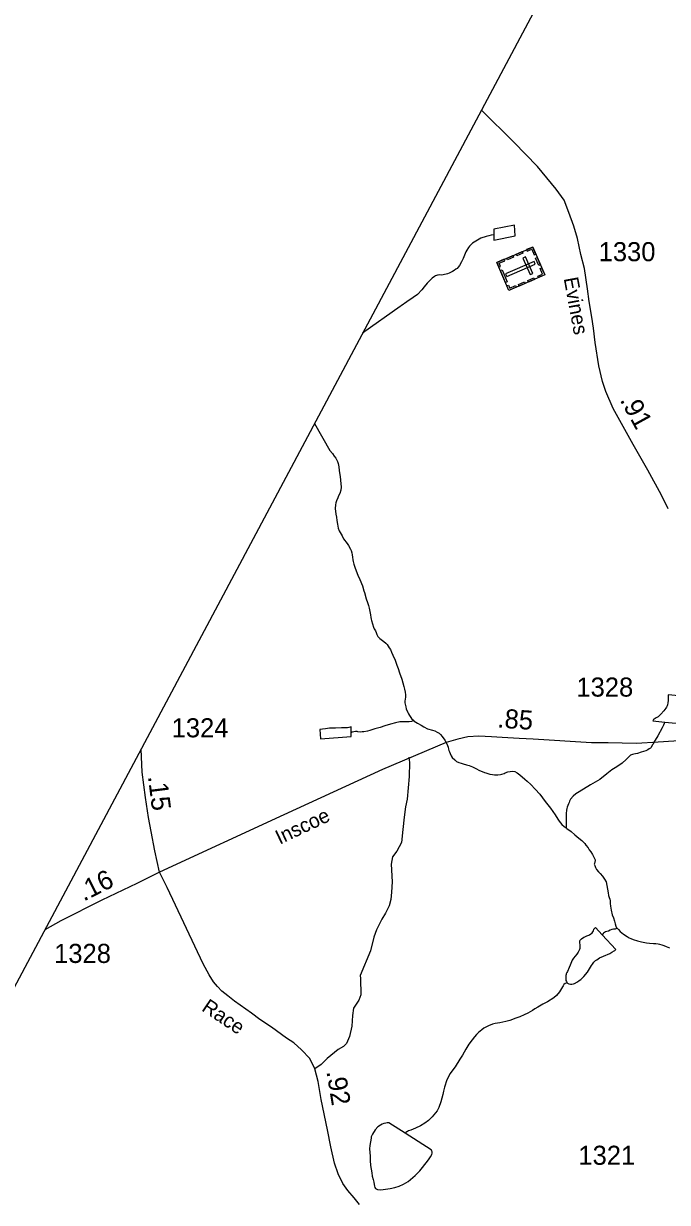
# Model space of a CAD drawing. Extents: x 2220236 to 2384410, y 720751 to 894131.
# Drawn here: x 2267666 to 2271879, y 844747 to 852462 of the extents above; entities that cross this region are included whole.
import ezdxf

# ---------------------------------------------------------------- set-up
doc = ezdxf.new("R2010")
doc.units = 0
for name, color, linetype in [('Exist Boundary Political CountyLine', 7, 'Continuous'), ('Exist Cultural Cemetery CELL', 7, 'Continuous'), ('Exist Hydrographic Creek Single Shore', 7, 'Continuous'), ('Exist Hydrographic Misc Water Feature', 7, 'Continuous'), ('Exist Hydrographic Pond Under 1500 Sq Ft', 7, 'Continuous'), ('Exist Road Non-System Type 51', 7, 'Continuous'), ('Exist Road Secondary Mileage Hundredths English Label', 7, 'Continuous'), ('Exist Road Secondary Type 51 Attributed', 7, 'Continuous'), ('Exist Road Secondary Type 51 Label', 7, 'Continuous'), ('Exist Road Secondary Type 51 Number Label', 7, 'Continuous')]:
    doc.layers.add(name, color=color, linetype=linetype)

msp = doc.modelspace()

# ---------------------------------------------------------------- linework, layer by layer
at = {"layer": 'Exist Boundary Political CountyLine'}
msp.add_lwpolyline([(2293117.8, 894131.3), (2291903.9, 891776.4), (2258821.6, 829664.6), (2255410.5, 823324), (2242088.6, 797598.7), (2231459.6, 775980.5), (2225010.8, 762953.2), (2220575.6, 753519.5)], dxfattribs=at)
at = {"layer": 'Exist Cultural Cemetery CELL'}
for points in [[(2270997.6, 850999.3), (2271076.4, 850816.5), (2270842.7, 850715.6), (2270763.8, 850898.4)], [(2270889.7, 850952.7), (2270929.5, 850969.9), (2270934, 850959.4), (2270894.2, 850942.3)], [(2270957.8, 850982.1), (2270962.3, 850971.7), (2270991.8, 850984.4), (2271007.9, 850947.2), (2271018.1, 850951.6), (2270997.6, 850999.3)], [(2270776.9, 850868), (2270787.5, 850872.6), (2270778.8, 850892.8), (2270815.9, 850908.8), (2270811.4, 850919), (2270763.8, 850898.4)], [(2271013.9, 850887.6), (2271006.5, 850904.7), (2270820.3, 850824.3), (2270827.7, 850807.2)], [(2270828, 850926.1), (2270867.7, 850943.3), (2270872.3, 850932.8), (2270832.5, 850915.7)], [(2270951.2, 850934.8), (2270934.1, 850927.4), (2270980.8, 850819.3), (2270997.9, 850826.7)], [(2271026.9, 850931.3), (2271047.4, 850883.7), (2271037, 850879.2), (2271016.4, 850926.7)], [(2270797.1, 850850.2), (2270830.7, 850772.2), (2270820.2, 850767.7), (2270786.6, 850845.6)], [(2271036.7, 850799.2), (2271032.2, 850809.6), (2271061.7, 850822.4), (2271045.6, 850859.6), (2271055.9, 850864), (2271076.4, 850816.4)], [(2270829.5, 850746), (2270840.1, 850750.5), (2270848.8, 850730.3), (2270885.9, 850746.4), (2270890.3, 850736.1), (2270842.7, 850715.6)], [(2270904.5, 850754.7), (2270944.3, 850771.8), (2270948.8, 850761.4), (2270909, 850744.2)], [(2270965, 850780.7), (2271004.8, 850797.9), (2271009.3, 850787.5), (2270969.6, 850770.3)]]:
    msp.add_lwpolyline(points, close=True, dxfattribs=at)
at = {"layer": 'Exist Hydrographic Creek Single Shore'}
for points in [[(2269569.9, 849844.6), (2269671.2, 849667.6), (2269687.5, 849647.6), (2269699.6, 849631.6), (2269708.9, 849617.6), (2269719.9, 849596.1), (2269723.9, 849581.9), (2269728.3, 849560.5), (2269730.4, 849535.8), (2269734.8, 849507.9), (2269736.9, 849498), (2269740.9, 849472.7), (2269743.6, 849428.3), (2269741.6, 849408.7), (2269735.9, 849386.5), (2269728, 849370.3), (2269722.2, 849358.2), (2269714.5, 849337.7), (2269709.7, 849324.7), (2269707.4, 849312.6), (2269706.7, 849306.1), (2269705.8, 849295.3), (2269705.6, 849285.4), (2269706.9, 849271.6), (2269708.8, 849251.9), (2269713.3, 849230.5), (2269715.5, 849209.8), (2269719.6, 849186.1), (2269725.9, 849160.4), (2269732.1, 849142.2), (2269738.1, 849129.9), (2269750.4, 849108.4), (2269760.5, 849088.5), (2269782.9, 849058.5), (2269793.1, 849045.2), (2269805.1, 849022.6), (2269809.1, 849012.7), (2269813.4, 848998.8), (2269817.4, 848984.6), (2269819.7, 848969.2), (2269821.7, 848952.7), (2269824, 848941.2), (2269828, 848924.7), (2269834.1, 848904.9), (2269842.5, 848880.8), (2269854.6, 848851), (2269866.9, 848823.9), (2269883.4, 848781.5), (2269893.5, 848749.5), (2269897.6, 848738), (2269907.8, 848695.8), (2269916.2, 848672), (2269922.4, 848653.8), (2269928.2, 848635.6), (2269932.7, 848614.2), (2269936.8, 848591.8), (2269939.1, 848573.7), (2269941.2, 848563.2), (2269942.7, 848555.6), (2269955.8, 848510.4), (2269961.5, 848500.5), (2269969.1, 848487.8), (2269973.8, 848476.3), (2269978.1, 848464), (2269984.4, 848450.8), (2269992.1, 848442.4), (2269998.6, 848436.4), (2270014.4, 848424.6), (2270024.4, 848417.2), (2270036.3, 848406.1), (2270045, 848397), (2270051.7, 848387.7), (2270059.6, 848376.1), (2270066.9, 848365.4), (2270073.2, 848348.9), (2270083.2, 848327.4), (2270097.6, 848294.9), (2270109.8, 848263.5), (2270118.2, 848241.4), (2270126.1, 848213.3), (2270140.7, 848172), (2270147.1, 848147.9), (2270153.5, 848124.2), (2270159.3, 848106), (2270163.5, 848086.3), (2270165.7, 848068.2), (2270165.8, 848054.1), (2270164.2, 848040.3), (2270162, 848027.9)], [(2270162, 848027.9), (2270162.2, 848022.3), (2270162, 848016.4), (2270164.2, 848007.5), (2270167.1, 847991.1), (2270170.4, 847977.9), (2270180.7, 847952.1), (2270184.5, 847943.8), (2270190.8, 847933.8), (2270201.1, 847920.5), (2270204.8, 847913.9), (2270220, 847899.8)], [(2270220, 847899.8), (2270223.2, 847896.4), (2270243.2, 847882.9), (2270267.6, 847869.3), (2270285.7, 847859), (2270310.4, 847847.1), (2270341.7, 847836.6), (2270357.6, 847832), (2270373.6, 847825.1), (2270385.9, 847817.6), (2270393.9, 847809.9), (2270406.1, 847795.9), (2270422, 847772.6), (2270436.3, 847748.3), (2270443.7, 847726.2), (2270447, 847713.7), (2270449.8, 847703.8), (2270452.9, 847694.9), (2270456.9, 847684.9), (2270463.8, 847669), (2270471.1, 847658.4), (2270487.5, 847643.3), (2270500.1, 847631.6), (2270515.4, 847624.7), (2270529.4, 847621.1), (2270543.8, 847617.5), (2270563.6, 847611.2), (2270581.6, 847605.9), (2270603.7, 847598.2), (2270611.8, 847593.8), (2270625.8, 847586.3), (2270649.8, 847574.3), (2270668, 847566.4), (2270682, 847560.5), (2270690.8, 847557.1), (2270718.1, 847549), (2270734.2, 847546.3), (2270748.2, 847545.1), (2270762.3, 847544.8), (2270770.2, 847545.6), (2270786.3, 847547.6), (2270795.9, 847550), (2270810.1, 847553.6), (2270818, 847557.7), (2270835.9, 847563.9), (2270850.4, 847567.5), (2270863.8, 847568.2), (2270881.8, 847566.2), (2270896.1, 847558.4), (2270913.9, 847544.9), (2270946.1, 847517.3), (2270962.5, 847502.9), (2270984.7, 847481.1), (2271014.9, 847452), (2271043.4, 847417.6), (2271079.5, 847370.3), (2271114, 847325.9), (2271144.3, 847284.3), (2271162.4, 847254.4), (2271170.7, 847242.7), (2271188.9, 847221), (2271203, 847207), (2271216, 847197.5)], [(2271216, 847197.5), (2271221.5, 847193.5), (2271249.3, 847173.9), (2271273.4, 847152), (2271299.8, 847130.2), (2271319.9, 847114.3), (2271337.9, 847096.6), (2271345.8, 847084.3), (2271360.2, 847066.6), (2271368.1, 847055), (2271378.4, 847041), (2271388.5, 847022.7), (2271402.7, 846996.8), (2271405.8, 846989.6), (2271407, 846984.6), (2271406.3, 846979.7), (2271404.9, 846974.8), (2271401.4, 846965), (2271401, 846960.8), (2271401.2, 846956.8), (2271403.4, 846950.9), (2271408.4, 846938.7), (2271415.3, 846925.4), (2271427.5, 846911), (2271439.7, 846899.3), (2271453.8, 846881), (2271468.1, 846862), (2271478.2, 846843.7), (2271490.9, 846772), (2271494.8, 846755.5), (2271496.9, 846748.2), (2271499.1, 846741.6), (2271503.1, 846731.7), (2271505.2, 846720.2), (2271505.5, 846702.1), (2271506.1, 846685.7), (2271510.5, 846658.4), (2271518.1, 846629.7), (2271526.2, 846608.2), (2271532.3, 846588.4), (2271536.8, 846570.3), (2271540.8, 846553.8), (2271546.8, 846544.5), (2271550.3, 846541.1)], [(2271550.3, 846541.1), (2271559, 846532.1), (2271570.9, 846520.4), (2271591.2, 846502.6), (2271615.5, 846486.6), (2271629.4, 846478.8), (2271639.8, 846473.7), (2271655.4, 846468.4), (2271683.8, 846459), (2271708.9, 846452.6), (2271741.6, 846446.3), (2271761.9, 846444.2), (2271787.7, 846442.1), (2271803.8, 846440.7), (2271819.8, 846438.8), (2271826.7, 846437), (2271841.7, 846432.7), (2271855, 846427.5), (2271871.3, 846421.3), (2271892.1, 846412)]]:
    msp.add_lwpolyline(points, dxfattribs=at)
at = {"layer": 'Exist Hydrographic Misc Water Feature'}
for points in [[(2270743.9, 851079.4), (2270725.8, 851077.5), (2270710.3, 851072.9), (2270694.1, 851068.9), (2270658.1, 851056.6), (2270636.5, 851044.9), (2270604.6, 851024.2), (2270594.6, 851016.2), (2270584.9, 851005.6), (2270577.1, 850995.9), (2270567, 850979.7), (2270560.5, 850967.7), (2270542.2, 850924.5), (2270531.9, 850901.7), (2270517.9, 850877.4), (2270509.9, 850867.1), (2270503.1, 850859.7), (2270494.2, 850853.3), (2270484.2, 850846.3), (2270472.5, 850839), (2270450.7, 850829), (2270440.4, 850824.9), (2270411.8, 850818.3), (2270398.3, 850816), (2270388.8, 850816.2), (2270380.2, 850815.7), (2270374.9, 850814.1), (2270362.7, 850810.1), (2270354.8, 850806.4), (2270340.8, 850795.8), (2270328.8, 850785.6), (2270307, 850763.7), (2270287.1, 850739.5), (2270271.6, 850719.5), (2270243.8, 850689), (2270216.1, 850668.9), (2270174.2, 850640.2), (2270136.6, 850614.1), (2270130.6, 850610), (2269884.7, 850435.5)], [(2270220, 847899.8), (2270203.8, 847893.5), (2270189.3, 847892.2), (2270175.2, 847892.5), (2270159.1, 847891.9), (2270143.1, 847891.5), (2270129.3, 847891.8), (2270099.3, 847884.9), (2270067.3, 847877.4), (2270029.3, 847865), (2269999, 847855.8), (2269965.6, 847846), (2269932, 847835.9), (2269916.1, 847831.3), (2269892.4, 847826.9), (2269881.9, 847825.4), (2269867.8, 847825.1), (2269854.1, 847827), (2269850.1, 847827.7), (2269842, 847828.9), (2269838, 847829), (2269827.8, 847826.6), (2269816.9, 847823.5), (2269810, 847820.4)], [(2271863.4, 847890.3), (2271857.9, 847880.5), (2271852.8, 847869.2), (2271844.9, 847852.9), (2271817.2, 847801), (2271799.3, 847772.5), (2271782.9, 847744.3), (2271779.9, 847738.5), (2271772, 847723.9), (2271768, 847720), (2271760.3, 847714.3), (2271750.7, 847707.9), (2271738.1, 847701.6), (2271707.1, 847692.4), (2271682.7, 847685.7), (2271670.5, 847683.4), (2271660.6, 847681.3), (2271650.4, 847678.2), (2271638.5, 847673.5), (2271624.8, 847660.7), (2271609.7, 847645.3), (2271582.9, 847620.6), (2271549.3, 847596.7), (2271515.4, 847577.7), (2271481.8, 847552.1), (2271436.4, 847513.7), (2271376.7, 847480.5), (2271300.9, 847434.5), (2271280.9, 847420.2), (2271263.3, 847405.8), (2271245.4, 847385.5), (2271239.3, 847373.5), (2271235.5, 847363.7), (2271231.7, 847355.6), (2271223.7, 847333.5), (2271221.5, 847323.7), (2271220, 847313.2), (2271216.9, 847291), (2271216.6, 847275.6), (2271216.6, 847261.5), (2271216.9, 847243.4), (2271216.6, 847229.6), (2271216, 847197.5)], [(2271550.3, 846541.1), (2271536.8, 846535.8), (2271526.9, 846534.4), (2271515.1, 846532), (2271504.8, 846528.3), (2271492.9, 846522.6), (2271483.3, 846519.6), (2271475.1, 846517.4), (2271467.8, 846513.3), (2271461.5, 846509.5), (2271459.1, 846506.9), (2271453.4, 846498.2)], [(2271222.5, 846183.8), (2271210.2, 846179.2), (2271201.9, 846172.1), (2271196.8, 846164.7), (2271192.4, 846156.6), (2271186.6, 846146.9), (2271173.7, 846125.8), (2271154.5, 846101.6), (2271137.1, 846086.6), (2271095.6, 846060.2), (2271073.4, 846047.5), (2271063.8, 846043.8), (2271041.9, 846031.8), (2271031.6, 846025.5), (2271012, 846013.7), (2270996, 846003.2), (2270966.1, 845985.2), (2270942.3, 845974.8), (2270914.5, 845962.3), (2270886.4, 845952.4), (2270848.7, 845937.4), (2270822.7, 845931.4), (2270783.1, 845921.7), (2270753.2, 845917.4), (2270735, 845912.9), (2270709.2, 845902.6), (2270687, 845892.5), (2270677.1, 845886.2), (2270665.4, 845876.6), (2270643.4, 845859.7), (2270629.7, 845846.2), (2270615.9, 845830.1), (2270602, 845809.7), (2270580.4, 845781.6), (2270560.4, 845749.2), (2270539, 845710.9), (2270521.4, 845685.1), (2270489.5, 845634.9), (2270475.6, 845614.8), (2270458.1, 845590.6), (2270442.7, 845561.4), (2270433.8, 845542.6), (2270422.6, 845508.4), (2270420.8, 845500.2), (2270419, 845492), (2270415, 845475.7), (2270409.3, 845453.9), (2270396.5, 845405.6), (2270383.9, 845367.5), (2270372.3, 845347), (2270341, 845306), (2270316.9, 845282.6), (2270292.6, 845266), (2270264, 845248.6), (2270231.2, 845231.9), (2270199.5, 845220.4), (2270185.6, 845214.1), (2270177.6, 845211.7), (2270167.7, 845205.3), (2270163.6, 845199.8)]]:
    msp.add_lwpolyline(points, dxfattribs=at)
at = {"layer": 'Exist Hydrographic Pond Under 1500 Sq Ft'}
for points in [[(2270743.9, 851079.4), (2270744.4, 851043.3), (2270882.1, 851072.6), (2270879.3, 851142.2), (2270743.6, 851115.5), (2270743.9, 851079.4)], [(2271863.4, 847890.3), (2271984.5, 847877.9), (2271999, 848058), (2271885.1, 848069.2), (2271884.8, 848053.8), (2271883.4, 848031.5), (2271881.4, 848016.8), (2271879.5, 848003.1), (2271877.4, 847997.2), (2271873.6, 847987.5), (2271869.5, 847981), (2271855.7, 847963.2), (2271836.6, 847942.3), (2271818.2, 847925.6), (2271806.2, 847918.3), (2271792.6, 847910.4), (2271787.6, 847906.6), (2271785.2, 847901.7), (2271784.5, 847898.5), (2271863.4, 847890.3)], [(2269810, 847820.4), (2269809.8, 847859.1), (2269795.6, 847854.5), (2269785.7, 847853), (2269747.6, 847852.2), (2269707.6, 847849.7), (2269667.6, 847849.6), (2269641.9, 847846.8), (2269622.2, 847843.3), (2269604.1, 847842.7), (2269608.4, 847781.3), (2269810.5, 847796.7), (2269810, 847820.4)], [(2271453.4, 846498.2), (2271409.1, 846546.7), (2271395, 846532.9), (2271392.9, 846524.7), (2271389.4, 846516.6), (2271383, 846506.9), (2271378.7, 846503), (2271369.4, 846496.7), (2271349.5, 846488.9), (2271333.3, 846480), (2271318, 846469.9), (2271313.3, 846467.3), (2271308, 846463.5), (2271305.6, 846460.3), (2271303.9, 846455.4), (2271303.8, 846450.5), (2271303.7, 846447.8), (2271305.7, 846430.7), (2271306.3, 846416), (2271305.2, 846408.5), (2271303.7, 846401.3), (2271294.5, 846384.1), (2271286.4, 846372.1), (2271264.9, 846345.3), (2271255.4, 846331.8), (2271243.2, 846299.2), (2271237.3, 846283.6), (2271225.6, 846257.6), (2271221.6, 846251.1), (2271217.5, 846242.3), (2271215.7, 846237.5), (2271214.3, 846230.9), (2271213.9, 846227.7), (2271213.8, 846223.4), (2271213.9, 846215.2), (2271214.1, 846207), (2271215.6, 846199.7), (2271218, 846191.5), (2271220.3, 846187.2), (2271222.5, 846183.8)], [(2271222.5, 846183.8), (2271225.7, 846180.5), (2271233.2, 846177.1), (2271244.6, 846175.2), (2271254.5, 846176), (2271264.3, 846177.4), (2271270.3, 846179.6), (2271290.2, 846190), (2271301.5, 846198), (2271311.8, 846205.9), (2271331.9, 846225.9), (2271355.5, 846254.2), (2271363.6, 846264.6), (2271383.2, 846297), (2271389, 846306.7), (2271398.8, 846318.9), (2271408.8, 846329.2), (2271416.8, 846335), (2271434.8, 846346.7), (2271460.3, 846359.3), (2271502.3, 846375.8), (2271516.2, 846383.7), (2271530.2, 846392.3), (2271536.2, 846396.4), (2271542.2, 846401.9), (2271453.4, 846498.2)], [(2270163.6, 845199.8), (2270056.8, 845268.3), (2270045.3, 845268.5), (2270037.7, 845266.4), (2270024.2, 845262.4), (2270012.3, 845257.8), (2270001.4, 845252.4), (2269985.4, 845241.9), (2269966, 845222.6), (2269950, 845193.4), (2269941.4, 845174.9), (2269939.9, 845167.4), (2269936.1, 845143.9), (2269932.3, 845119.4), (2269930.9, 845098.1), (2269933, 845073.4), (2269933.2, 845049.5), (2269933.6, 845021.6), (2269935.9, 844988.1), (2269944.1, 844941), (2269948.2, 844918), (2269954.6, 844897.5), (2269958.5, 844880), (2269960.8, 844864.6), (2269962.9, 844852.1), (2269965, 844843.8), (2269969.2, 844838.1), (2269982.8, 844832), (2270001.4, 844828.3), (2270018.8, 844830.6), (2270064.9, 844836.8), (2270095.2, 844843.7), (2270124.9, 844853), (2270152.7, 844865.5), (2270182.3, 844883.6), (2270229.7, 844922.9), (2270258.2, 844952.5), (2270276, 844974.5), (2270315.4, 845024.5), (2270329, 845045.5), (2270336.9, 845060.8), (2270339, 845068.3), (2270339.8, 845075.5), (2270339.9, 845078.8), (2270338.6, 845083), (2270335.5, 845088), (2270332.6, 845091.4), (2270163.6, 845199.8)]]:
    msp.add_lwpolyline(points, dxfattribs=at)
at = {"layer": 'Exist Road Non-System Type 51'}
msp.add_lwpolyline([(2270187.6, 847660.8), (2270192, 847625.2), (2270190.5, 847534.8), (2270175.7, 847386.6), (2270164.6, 847334.7), (2270155.7, 847268), (2270147.6, 847187.9), (2270138.7, 847101.9), (2270109.1, 847045.6), (2270080.9, 847008.6), (2270072, 846959.6), (2270077.7, 846844.5), (2270074.3, 846776.4), (2270068.9, 846728.3), (2270059.3, 846688.3), (2270035.7, 846640.2), (2270010, 846600), (2269976.6, 846531.7), (2269957.2, 846483.5), (2269937.2, 846393.4), (2269869.1, 846231.8), (2269870.5, 846211.1), (2269872.8, 846105.8), (2269860.9, 846070.2), (2269825.4, 846018.4), (2269818, 845969.4), (2269815, 845899.8), (2269798.7, 845833.1), (2269779.4, 845787.1), (2269760.2, 845767.8), (2269724.6, 845747.1), (2269652, 845687.8), (2269628.3, 845664.1), (2269613.5, 845649.3), (2269572.8, 845621.1)], dxfattribs=at)
at = {"layer": 'Exist Road Secondary Type 51 Attributed'}
for points in [[(2271884.5, 849285.4), (2271840.1, 849375.9), (2271751.2, 849538.9), (2271654.1, 849707.9), (2271525.3, 849942.1), (2271477.1, 850053.3), (2271454.9, 850120), (2271431.2, 850220.8), (2271407.5, 850374.9), (2271395.6, 850468.3), (2271385.3, 850541), (2271367.5, 850643.2), (2271357.1, 850724.8), (2271336.4, 850859.7), (2271312.7, 850950.1), (2271289.9, 851054.8), (2271266.3, 851136.7), (2271234.6, 851224.6), (2271202.9, 851305.5), (2271150.7, 851378.1), (2271029, 851525.4), (2270873.8, 851685.8), (2270662, 851894.8)], [(2272834.1, 847761.6), (2272751.1, 847776.4), (2272570.4, 847792.7), (2272305.9, 847789), (2272158, 847781.7), (2271818.4, 847758.4), (2271676.5, 847751.1), (2271582.6, 847752.3), (2271492.6, 847753.4), (2271383, 847754.2), (2271001.6, 847777.9), (2270909.7, 847782.3), (2270798.6, 847789.8), (2270728.3, 847792.7), (2270645.3, 847798.6), (2270572.7, 847794.2), (2270507.5, 847779.4), (2270431.5, 847756.4), (2270014.2, 847580.7), (2269369.8, 847282.8), (2268555.4, 846907)], [(2268555.4, 846907), (2268524.2, 847047.6), (2268500.7, 847174.2), (2268484, 847266), (2268465, 847397.1), (2268443.3, 847561.7), (2268434.8, 847713.3)], [(2268555.4, 846907), (2268406.5, 846832.8), (2268178.1, 846723.8), (2267911.1, 846589.2), (2267805.3, 846531.4)], [(2269864.6, 844733.2), (2269829.1, 844776.2), (2269789.1, 844825.1), (2269756.5, 844869.6), (2269725.4, 844933.3), (2269701.7, 845004.4), (2269676.5, 845111.2), (2269654.3, 845222.3), (2269614.3, 845419.5), (2269595, 845538.1), (2269572.8, 845621.1), (2269538.7, 845687.8), (2269484.2, 845745.3), (2269434, 845790.9), (2269387.6, 845822.5), (2269288.9, 845893.5), (2269212.6, 845944.7), (2269158.3, 845984.2), (2269046.2, 846062.8), (2269003.2, 846098.4), (2268964.7, 846129.5), (2268935, 846160.7), (2268908.4, 846190.3), (2268881.7, 846236.3), (2268841.7, 846307.4), (2268605.2, 846807.5), (2268555.4, 846907)]]:
    msp.add_lwpolyline(points, dxfattribs=at)

# ---------------------------------------------------------------- texts
at = {"layer": 'Exist Road Secondary Mileage Hundredths English Label'}
for s, rotation, p in [('.91', 298.82321, (2271565.6, 849998.5)), ('.85', 356.18365, (2270764.2, 847854.7)), ('.15', 277.15516, (2268479.6, 847534.6)), ('.16', 26.74543, (2268060.2, 846715.4)), ('.92', 279.22432, (2269647.7, 845603.3))]:
    msp.add_text(s, height=125, rotation=rotation, dxfattribs=at).set_placement(p)
at = {"layer": 'Exist Road Secondary Type 51 Label'}
for s, rotation, p in [('Evines', 280.43655, (2271200.3, 850794.1)), ('Inscoe', 25.35054, (2269342.2, 847086.8)), ('Race', 326.23237, (2268825.9, 846005.8))]:
    msp.add_text(s, height=95, rotation=rotation, dxfattribs=at).set_placement(p)
at = {"layer": 'Exist Road Secondary Type 51 Number Label'}
for s, p in [('1330', (2271429.3, 850906.4)), ('1328', (2271283.7, 848056.9)), ('1324', (2268635.3, 847790.4)), ('1328', (2267866.3, 846313.9)), ('1321', (2271296.6, 844992.7))]:
    msp.add_text(s, height=125, dxfattribs=at).set_placement(p)

doc.saveas('drawing.dxf')
